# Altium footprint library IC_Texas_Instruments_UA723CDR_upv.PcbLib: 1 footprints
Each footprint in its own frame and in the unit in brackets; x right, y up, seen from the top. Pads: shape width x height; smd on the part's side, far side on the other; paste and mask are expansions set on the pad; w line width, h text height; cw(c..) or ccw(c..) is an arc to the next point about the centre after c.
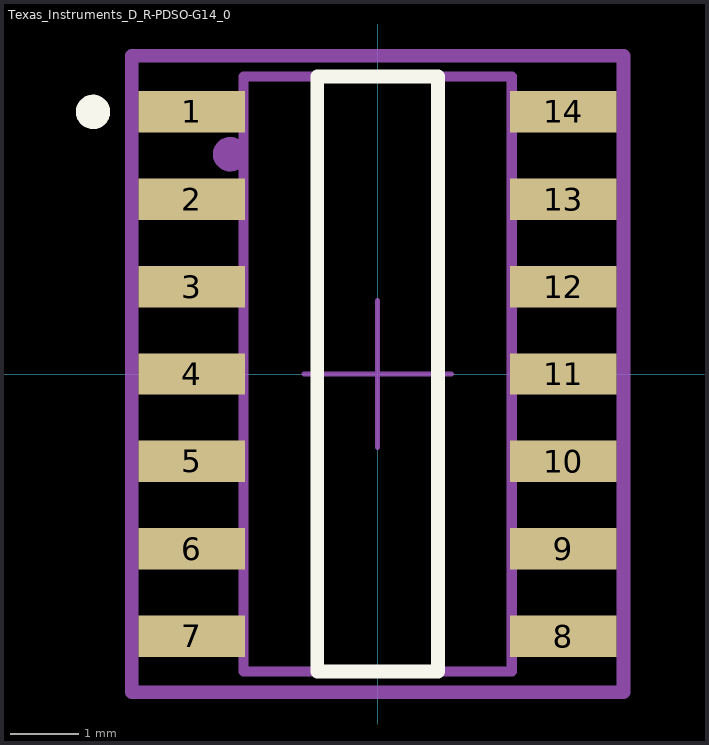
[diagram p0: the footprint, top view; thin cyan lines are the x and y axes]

## Texas_Instruments_D_R-PDSO-G14_0 [mm]
pads (28):
  rect 1.55x0.6 smd: 1(-2.7,3.81) 2(-2.7,2.54) 3(-2.7,1.27) 4(-2.7,0) 5(-2.7,-1.27) 6(-2.7,-2.54) 7(-2.7,-3.81) 8(2.7,-3.81) 9(2.7,-2.54) 10(2.7,-1.27) 11(2.7,0) 12(2.7,1.27) 13(2.7,2.54) 14(2.7,3.81)
  rect 1.5x0.55 on Top Paste: ""(-2.7,-3.81) ""(-2.7,-2.54) ""(-2.7,-1.27) ""(-2.7,0) ""(-2.7,1.27) ""(-2.7,2.54) ""(-2.7,3.81) ""(2.7,-3.81) ""(2.7,-2.54) ""(2.7,-1.27) ""(2.7,0) ""(2.7,1.27) ""(2.7,2.54) ""(2.7,3.81)
Top Overlay:
  circle w0.25: c-4.137,3.81 r0.125
  lines w0.2: -0.879,-4.325 -0.879,4.325 0.879,4.325 0.879,-4.325 -0.879,-4.325
Mechanical 10:
  circle w0.25: c-2.145,3.195 r0.125
  lines w0.2: -3.575,-4.625 3.575,-4.625 3.575,4.625 -3.575,4.625 -3.575,-4.625
  text ".Designator" at 0,0 h1
Mechanical 12:
  lines w0.15: -1.95,-4.325 -1.95,4.325 1.95,4.325 1.95,-4.325 -1.95,-4.325
Mechanical 15:
  lines w0.07: -1.072,0 1.072,0 -1.072,0 ; 0,-1.072 0,1.072 0,-1.072
  lines w0.1: -3.575,-4.625 -3.575,4.625 3.575,4.625 3.575,-4.625 -3.575,-4.625
3D body "IC_UA723CDR_upv.STEP": height 2.05, standoff 0, extent -3,-4.325 3,4.325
